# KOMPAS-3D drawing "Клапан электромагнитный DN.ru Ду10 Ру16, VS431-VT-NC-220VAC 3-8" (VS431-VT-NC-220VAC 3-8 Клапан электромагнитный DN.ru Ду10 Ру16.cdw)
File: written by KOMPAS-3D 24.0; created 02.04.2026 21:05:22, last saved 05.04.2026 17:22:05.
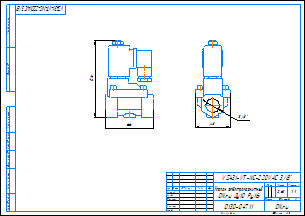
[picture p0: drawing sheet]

Document properties: c3d_UniqueCompID: ef56311e-7521-43dc-8291-0e6108b3d81d; Обозначение: VS400-ET-NC-220VAC 3-8; Наименование: Клапан электромагнитный DN.ru Ду10 Ру16; Автор: artio; Класс точности: c; Знак неуказанной шероховатости: Шероховатость не задана; Рассекать на разрезах: Да; Автор: artio; Форматы листов документа: A3; Полное имя файла: VS431-VT-NC-220VAC 3-8 Клапан электромагнитный DN.ru Ду10 Ру16.m3d; Масса: 0.62; Наименование: Клапан электромагнитный DN.ru Ду10 Ру16; Количество листов документа: 1; Примечание: D130-04711

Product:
- Body: Тело 1  | qty 1
    Масса: 1.030062
- Part/product: Клапан электромагнитный DN.ru Ду10 Ру16  | designation VS431-VT-NC-220VAC 3-8
    Масса: 0.62
    Раздел спецификации: Прочие изделия
    Примечание: D130-04711
    additional columns: ef56311e-7521-43dc-8291-0e6108b3d81d; VS400-ET-NC-220VAC 3-8; artio; c; Шероховатость не задана; Да

Views: Вид 1, Спереди, Проекционный вид 2
Referenced files in C:\Users\artio\OneDrive\Рабочий стол\Клапан электромагнитный DN.ru VS4x-xT-NC-x\DN10\: VS400-ET-NC-220VAC 3-8 Клапан электромагнитный DN.ru Ду10 Ру16.m3d
Referenced files in C:\Users\artio\OneDrive\Рабочий стол\Клапан электромагнитный DN.ru\VS431\VS431-VT-NC\VS431-VT-NC-220VAC\Ду10\: VS431-VT-NC-220VAC 3-8 Клапан электромагнитный DN.ru Ду10 Ру16.m3d
Referenced files in C:\Users\artio\OneDrive\Рабочий стол\Клапан электромагнитный DN.ru\VS400-VT-NC\VS400-VT-NC-220VAC\: VS400-VT-NC-220VAC 3-8 Клапан электромагнитный DN.ru Ду10 Ру16.cdw
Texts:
  VS431-VT-NC-220VAC 3-8
  Линейный размер
  Клапан электромагнитный
  DN.ru Ду10 Ру16
  VS431-VT-NC-220VAC 3/8"
  VS431-VT-NC-220VAC 3/8"-
  Клапан электромагнитный DN.ru Ду10 Ру16
  VS431-VT-NC-220VAC 3-8 Клапан электромагнитный DN.ru Ду10 Ру16
Dimensions and other numbers on the sheet: 0; 3; 2; 4; 48; 3/8"; 66; 106; 1:1; 1; 0,62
